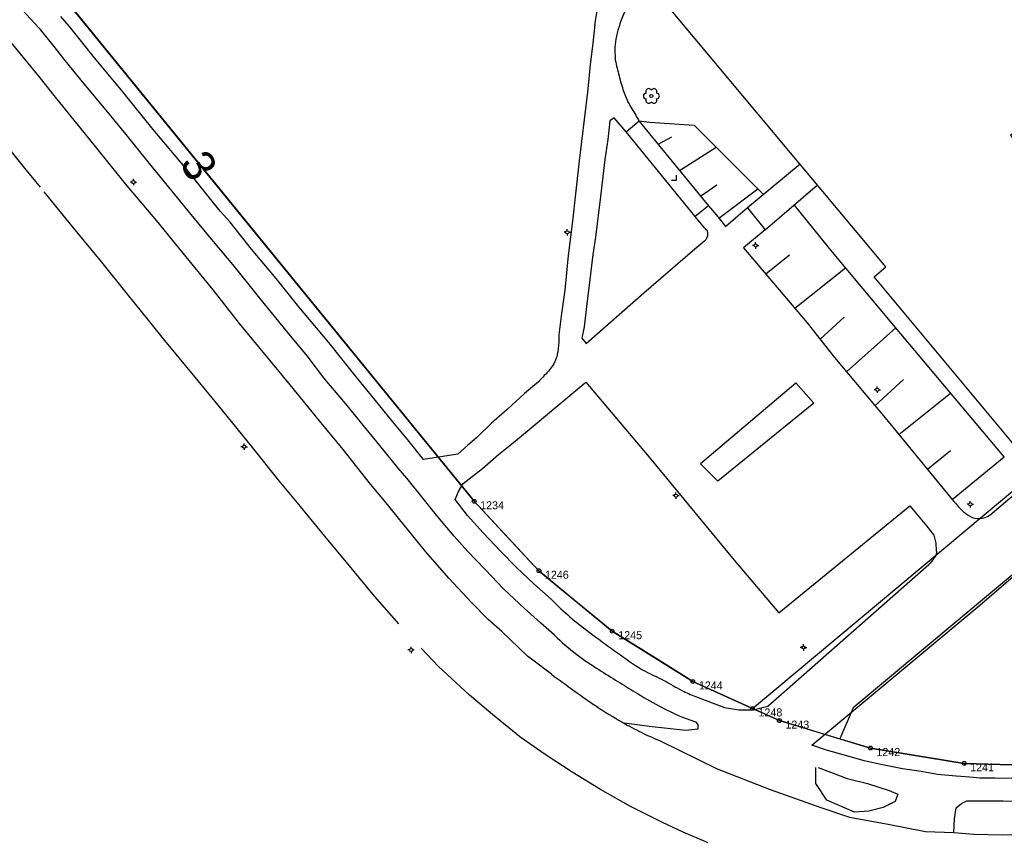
# Model space of a CAD drawing. Extents: x 1517478 to 1518189, y 6494860 to 6495389.
# Drawn here: x 1517715.6 to 1517838.6, y 6494947.3 to 6495049.6 of the extents above; entities that cross this region are included whole.
import ezdxf

# ---------------------------------------------------------------- set-up
doc = ezdxf.new("R2010")
doc.units = 0
for name, color, linetype in [('adress', 7, 'Continuous'), ('allmanbyggnad', 7, 'Continuous'), ('bro', 7, 'Continuous'), ('gc_vag', 7, 'Continuous'), ('grans', 7, 'Continuous'), ('granspunkt', 7, 'Continuous'), ('granspunkt_text', 7, 'Continuous'), ('kvartersgrans', 7, 'Continuous'), ('kvartersytor', 7, 'Continuous'), ('lovtrad', 7, 'Continuous'), ('parkeringskant', 7, 'Continuous'), ('rattighet_grans_ANV_EJ', 7, 'Continuous'), ('slant_skraffering', 7, 'Continuous'), ('slantfot', 7, 'Continuous'), ('stodmur', 7, 'Continuous'), ('stolpe_belysning', 7, 'Continuous'), ('trappa', 7, 'Continuous'), ('trappsymbol', 7, 'Continuous'), ('vagkant', 7, 'Continuous'), ('vagkant_mindre', 7, 'Continuous')]:
    doc.layers.add(name, color=color, linetype=linetype)

msp = doc.modelspace()

# ---------------------------------------------------------------- linework, layer by layer
at = {"layer": 'allmanbyggnad'}
msp.add_lwpolyline([(1517795.98, 6495052.03), (1517837.72, 6495086.69), (1517844.24, 6495078.9), (1517844.89, 6495079.4), (1517856.96, 6495064.93), (1517856.28, 6495064.33), (1517862.19, 6495057.11), (1517842.98, 6495041.23), (1517844.57, 6495039.29), (1517839.38, 6495035.07), (1517847.33, 6495025.71), (1517853.22, 6495030.6), (1517862.35, 6495019.75), (1517850.98, 6495010.13), (1517853.38, 6495007.24), (1517840.06, 6494996.19), (1517822.37, 6495017.44), (1517823.84, 6495018.69), (1517795.97, 6495052.03)], dxfattribs=at)
at = {"layer": 'bro'}
msp.add_lwpolyline([(1517813.13, 6495031.51), (1517806.55, 6495026.04), (1517808.74, 6495023.31), (1517815.3, 6495028.91)], dxfattribs=at)
at = {"layer": 'gc_vag'}
for p, q in [((1517782.84, 6495001.34), (1517786.35, 6495004.25)), ((1517783.24, 6494975.95), (1517782, 6494977.16))]:
    msp.add_line(p, q, dxfattribs=at)
for points in [[(1517718.21, 6495048.34), (1517718.04, 6495048.55), (1517715.97, 6495050.73), (1517714.5, 6495052.16), (1517712.54, 6495053.95), (1517710.97, 6495055.35), (1517708.65, 6495057.17), (1517706.66, 6495058.85), (1517705.01, 6495060.19), (1517703.14, 6495061.88)], [(1517724.81, 6495044.99), (1517723.5, 6495046.63), (1517721.86, 6495048.69), (1517720.78, 6495049.96)], [(1517721.14, 6495044.68), (1517719.93, 6495046.21), (1517718.21, 6495048.34)], [(1517787.46, 6495048.97), (1517787.21, 6495046.63), (1517786.9, 6495043.91)], [(1517737.05, 6495025.22), (1517731.83, 6495031.58), (1517728.92, 6495035.22), (1517726.43, 6495038.23), (1517723.49, 6495041.77), (1517721.14, 6495044.68)], [(1517740.66, 6495025.65), (1517736.52, 6495030.84), (1517732.32, 6495035.85), (1517728.5, 6495040.55), (1517724.81, 6495044.99)], [(1517786.9, 6495043.91), (1517786.54, 6495040.51), (1517786.18, 6495037.43), (1517785.79, 6495034.34), (1517785.53, 6495031.93)], [(1517791.38, 6495035.56), (1517789.88, 6495037.27), (1517789.36, 6495036.91), (1517789.08, 6495034.58), (1517788.74, 6495032.09)], [(1517785.53, 6495031.93), (1517785.06, 6495027.78), (1517784.67, 6495024.39), (1517784.16, 6495020.11)], [(1517788.74, 6495032.09), (1517788.2, 6495027.45), (1517787.55, 6495022.39), (1517787.24, 6495020.21)], [(1517801.66, 6495026.31), (1517802.68, 6495025.15), (1517803.84, 6495023.66)], [(1517753.76, 6495004.65), (1517751.53, 6495007.54), (1517749.08, 6495010.52), (1517745.64, 6495014.76), (1517742.46, 6495018.72), (1517739.62, 6495022.1), (1517737.05, 6495025.22)], [(1517757.49, 6495005.15), (1517754.23, 6495009.22), (1517750.51, 6495013.67), (1517747.68, 6495017.21), (1517744.59, 6495020.89), (1517741.9, 6495024.25), (1517740.66, 6495025.65)], [(1517801.2, 6495023.49), (1517800.55, 6495024.28), (1517800, 6495024.96)], [(1517784.16, 6495020.11), (1517783.72, 6495015.78), (1517783.33, 6495012.85), (1517782.99, 6495010.18), (1517782.96, 6495009.28)], [(1517787.24, 6495020.21), (1517786.85, 6495017.1), (1517786.46, 6495014.07), (1517786.15, 6495011.19), (1517785.87, 6495009.77), (1517786.38, 6495009.1)], [(1517780.43, 6495004.32), (1517778.67, 6495002.85), (1517776.54, 6495000.85), (1517774.58, 6494999.13), (1517772.72, 6494997.34), (1517771.6, 6494996.4), (1517770.34, 6494995.28), (1517766.07, 6494994.61), (1517764.1, 6494997.06), (1517762.25, 6494999.31), (1517758.99, 6495003.29), (1517757.49, 6495005.15)], [(1517760.6, 6494996.36), (1517758.17, 6494999.37), (1517756.35, 6495001.55), (1517753.76, 6495004.65)], [(1517777.33, 6494996.75), (1517780.01, 6494998.96), (1517782.84, 6495001.34)], [(1517778.68, 6494976.01), (1517776.07, 6494978.46), (1517773.82, 6494980.84), (1517771.58, 6494983.15), (1517769.9, 6494985.01), (1517767.87, 6494987.43), (1517766.05, 6494989.74), (1517763.98, 6494992.26), (1517762.92, 6494993.54), (1517760.6, 6494996.36)], [(1517782, 6494977.16), (1517779.85, 6494979.09), (1517777.68, 6494981.12), (1517775.68, 6494983.15), (1517773.54, 6494985.43), (1517771.58, 6494987.6), (1517770.04, 6494989.6), (1517770.43, 6494990.62), (1517771.02, 6494991.6), (1517773.44, 6494993.49), (1517775.43, 6494995.24), (1517777.33, 6494996.75)], [(1517782.42, 6494972.66), (1517780.67, 6494974.22), (1517778.68, 6494976.01)], [(1517800.05, 6494964.98), (1517803.66, 6494963.63), (1517805.46, 6494963.33), (1517807.27, 6494963.33), (1517809.07, 6494963.78)], [(1517798.28, 6494962.48), (1517800.05, 6494961.83), (1517800.35, 6494961.52), (1517800.35, 6494960.92), (1517798.85, 6494960.77), (1517794.64, 6494961.22), (1517791.15, 6494961.65)], [(1517821.11, 6494956.98), (1517818.95, 6494957.58), (1517816.43, 6494958.31), (1517814.6, 6494958.94)], [(1517834.33, 6494954.91), (1517832.63, 6494955.05), (1517830.29, 6494955.26), (1517828.25, 6494955.61), (1517825.91, 6494955.97), (1517823.39, 6494956.46), (1517821.11, 6494956.98)], [(1517815.39, 6494956.11), (1517819, 6494954.76), (1517821.55, 6494954.15), (1517824.26, 6494953.25), (1517825.31, 6494952.8), (1517825.01, 6494951.9), (1517823.51, 6494951.15), (1517821.7, 6494950.69), (1517819.9, 6494950.54), (1517816.44, 6494952.05), (1517815.09, 6494954.15), (1517815.09, 6494956.11)], [(1517862.88, 6494955.09), (1517860.81, 6494955.05), (1517858.46, 6494954.98), (1517854.75, 6494954.91), (1517851, 6494954.84), (1517847.43, 6494954.88), (1517844.03, 6494954.84), (1517840.85, 6494954.74), (1517837.48, 6494954.81), (1517835.56, 6494954.81), (1517834.33, 6494954.91)], [(1517832.31, 6494947.99), (1517832.41, 6494949.71), (1517832.62, 6494951.11), (1517833.29, 6494951.63), (1517833.95, 6494951.95), (1517838.47, 6494951.95), (1517843.09, 6494951.84), (1517849.01, 6494951.84), (1517853.81, 6494951.88)]]:
    msp.add_lwpolyline(points, dxfattribs=at)
for points in [[(1517786.77, 6495054.17), (1517787.37, 6495053), (1517787.7, 6495051.97), (1517787.73, 6495050.93), (1517787.44, 6495048.88)], [(1517792.29, 6495052.15), (1517791.1, 6495050.31), (1517790.48, 6495048.62), (1517790.09, 6495047.12), (1517789.98, 6495045.77), (1517790.03, 6495044.42)], [(1517790.03, 6495044.5), (1517790.5, 6495042.53), (1517791.07, 6495040.61), (1517791.75, 6495039.03), (1517792.7, 6495037.43), (1517792.99, 6495036.91)], [(1517801.22, 6495021.95), (1517801.47, 6495022.27), (1517801.59, 6495022.68), (1517801.55, 6495023.09), (1517801.19, 6495023.5)], [(1517782.96, 6495009.28), (1517782.77, 6495007.72), (1517782.46, 6495006.81), (1517782.2, 6495006.32), (1517781.68, 6495005.65), (1517780.98, 6495004.9), (1517780.43, 6495004.32)], [(1517783.24, 6494975.95), (1517785.52, 6494973.99), (1517787.71, 6494972.33), (1517790.68, 6494970.19), (1517793.75, 6494968.16), (1517796.09, 6494967.01), (1517798.33, 6494965.76), (1517800.05, 6494964.98)], [(1517782.42, 6494972.66), (1517785.21, 6494970.24), (1517787.97, 6494968.37), (1517790.36, 6494966.86), (1517792.5, 6494965.55), (1517795.47, 6494963.83), (1517798.28, 6494962.48)]]:
    msp.add_spline(points, degree=3, dxfattribs=at)
at = {"layer": 'grans'}
for p, q in [((1517807.17, 6494963.51), (1517919.72, 6495057.58)), ((1517718.21, 6495055.89), (1517772.4, 6494989.39)), ((1517772.4, 6494989.39), (1517780.49, 6494980.71)), ((1517780.49, 6494980.71), (1517789.65, 6494973.16)), ((1517789.65, 6494973.16), (1517799.72, 6494966.88)), ((1517799.72, 6494966.88), (1517807.17, 6494963.51)), ((1517807.17, 6494963.51), (1517810.53, 6494961.99)), ((1517810.53, 6494961.99), (1517821.9, 6494958.56)), ((1517821.9, 6494958.56), (1517833.61, 6494956.65)), ((1517833.61, 6494956.65), (1517845.48, 6494956.3))]:
    msp.add_line(p, q, dxfattribs=at)
at = {"layer": 'granspunkt'}
for centre in [(1517772.4, 6494989.39), (1517780.49, 6494980.71), (1517789.65, 6494973.16), (1517799.72, 6494966.88), (1517807.17, 6494963.51), (1517810.53, 6494961.99), (1517821.9, 6494958.56), (1517833.61, 6494956.65)]:
    msp.add_circle(centre, 0.237, dxfattribs=at)
at = {"layer": 'kvartersgrans'}
for points in [[(1517718.21, 6495055.89), (1517772.4, 6494989.39), (1517780.49, 6494980.71), (1517789.65, 6494973.16), (1517799.72, 6494966.88)], [(1517799.72, 6494966.88), (1517807.17, 6494963.51), (1517810.53, 6494961.99)], [(1517810.53, 6494961.99), (1517821.9, 6494958.56), (1517833.61, 6494956.65), (1517845.48, 6494956.3), (1517968.3, 6494960.82), (1517976.46, 6494961.8), (1517984.36, 6494964.1), (1517991.77, 6494967.66)]]:
    msp.add_lwpolyline(points, dxfattribs=at)
at = {"layer": 'kvartersytor'}
msp.add_lwpolyline([(1517845.48, 6494956.3), (1517833.61, 6494956.65), (1517821.9, 6494958.56), (1517816.22, 6494960.27), (1517810.53, 6494961.99), (1517807.17, 6494963.51), (1517799.72, 6494966.88), (1517794.69, 6494970.02), (1517789.65, 6494973.16), (1517785.07, 6494976.93), (1517780.49, 6494980.71), (1517776.44, 6494985.05), (1517772.4, 6494989.39), (1517745.3, 6495022.64), (1517717, 6495057.37), (1517819.97, 6495111.05)], dxfattribs=at)
at = {"layer": 'lovtrad'}
msp.add_circle((1517794.53, 6495040.02), 0.2, dxfattribs=at)
for centre, start, end in [((1517794.21, 6495040.57), 29.1347, 212.3057), ((1517794.85, 6495040.57), 329.1331, 150.8613), ((1517793.9, 6495040.01), 89.5389, 268.9887), ((1517794.21, 6495039.47), 150.5831, 330.865), ((1517794.85, 6495039.47), 209.1844, 30.8583), ((1517795.17, 6495040.02), 269.1508, 90.8733)]:
    msp.add_arc(centre, 0.366, start, end, dxfattribs=at)
at = {"layer": 'parkeringskant'}
msp.add_line((1517806.06, 6495021.07), (1517813.99, 6495011.69), dxfattribs=at)
for points in [[(1517786.38, 6495009.1), (1517793.6, 6495015.42), (1517799.97, 6495020.92), (1517801.22, 6495021.95)], [(1517813.99, 6495011.69), (1517817.41, 6495007.33), (1517823.73, 6494999.82), (1517832.13, 6494989.6)], [(1517786.35, 6495004.25), (1517794.25, 6494994.89), (1517804.87, 6494982.04)], [(1517800.68, 6494994.11), (1517812.59, 6495004.17), (1517814.82, 6495001.63), (1517802.85, 6494991.89), (1517800.68, 6494994.06)], [(1517804.87, 6494982.04), (1517810.44, 6494975.45), (1517826.82, 6494988.83)]]:
    msp.add_lwpolyline(points, dxfattribs=at)
at = {"layer": 'rattighet_grans_ANV_EJ'}
for p, q in [((1517924.99, 6495051.56), (1517819.73, 6494963.58)), ((1517819.73, 6494963.58), (1517818.07, 6494959.71))]:
    msp.add_line(p, q, dxfattribs=at)
at = {"layer": 'slant_skraffering'}
for p, q in [((1517795.39, 6495033.98), (1517797.09, 6495034.91)), ((1517798.06, 6495030.71), (1517802.63, 6495033.63)), ((1517800.68, 6495027.51), (1517802.71, 6495028.92)), ((1517802.97, 6495024.77), (1517807.84, 6495028.42)), ((1517808.82, 6495017.81), (1517811.81, 6495020.18)), ((1517812.44, 6495013.52), (1517818.8, 6495018.56)), ((1517815.62, 6495009.62), (1517818.63, 6495012.39)), ((1517818.92, 6495005.54), (1517825.06, 6495011.05)), ((1517822.47, 6495001.32), (1517826.05, 6495004.61)), ((1517825.45, 6494997.73), (1517831.92, 6495002.89)), ((1517829.03, 6494993.38), (1517831.92, 6494995.75))]:
    msp.add_line(p, q, dxfattribs=at)
at = {"layer": 'slantfot'}
for points in [[(1517792.98, 6495036.92), (1517794.29, 6495036.76), (1517799.9, 6495036.37), (1517808.6, 6495027.66)], [(1517824.82, 6495011.33), (1517817.18, 6495020.5), (1517812.41, 6495026.36)], [(1517832.13, 6494989.6), (1517838.61, 6494994.94), (1517824.82, 6495011.33)]]:
    msp.add_lwpolyline(points, dxfattribs=at)
at = {"layer": 'stodmur'}
for p, q in [((1517806.55, 6495026.04), (1517803.85, 6495023.73)), ((1517808.74, 6495023.31), (1517806.04, 6495021.07))]:
    msp.add_line(p, q, dxfattribs=at)
at = {"layer": 'stolpe_belysning'}
for p, q in [((1517729.84, 6495029.46), (1517729.84, 6495029.66)), ((1517729.64, 6495029.26), (1517729.44, 6495029.26)), ((1517729.84, 6495029.06), (1517729.84, 6495028.86)), ((1517730.04, 6495029.26), (1517730.24, 6495029.26)), ((1517784.03, 6495023.19), (1517784.03, 6495023.39)), ((1517783.83, 6495022.99), (1517783.63, 6495022.99)), ((1517784.03, 6495022.79), (1517784.03, 6495022.59)), ((1517784.23, 6495022.99), (1517784.43, 6495022.99)), ((1517807.36, 6495021.34), (1517807.16, 6495021.34)), ((1517807.56, 6495021.54), (1517807.56, 6495021.74)), ((1517807.56, 6495021.14), (1517807.56, 6495020.94)), ((1517807.76, 6495021.34), (1517807.96, 6495021.34)), ((1517822.76, 6495003.52), (1517822.76, 6495003.72)), ((1517822.56, 6495003.32), (1517822.36, 6495003.32)), ((1517822.76, 6495003.12), (1517822.76, 6495002.92)), ((1517822.96, 6495003.32), (1517823.16, 6495003.32)), ((1517743.67, 6494996.4), (1517743.67, 6494996.6)), ((1517743.47, 6494996.2), (1517743.27, 6494996.2)), ((1517743.67, 6494996), (1517743.67, 6494995.8)), ((1517743.87, 6494996.2), (1517744.07, 6494996.2)), ((1517797.4, 6494990.09), (1517797.2, 6494990.09)), ((1517797.6, 6494990.29), (1517797.6, 6494990.49)), ((1517797.8, 6494990.09), (1517798, 6494990.09)), ((1517797.6, 6494989.89), (1517797.6, 6494989.69)), ((1517834.18, 6494989.02), (1517833.98, 6494989.02)), ((1517834.38, 6494989.22), (1517834.38, 6494989.42)), ((1517834.58, 6494989.02), (1517834.78, 6494989.02)), ((1517834.38, 6494988.82), (1517834.38, 6494988.62)), ((1517764.32, 6494970.81), (1517764.12, 6494970.81)), ((1517764.52, 6494971.01), (1517764.52, 6494971.21)), ((1517764.52, 6494970.61), (1517764.52, 6494970.41)), ((1517764.72, 6494970.81), (1517764.92, 6494970.81)), ((1517813.34, 6494971.12), (1517813.14, 6494971.12)), ((1517813.54, 6494971.32), (1517813.54, 6494971.52)), ((1517813.54, 6494970.92), (1517813.54, 6494970.72)), ((1517813.74, 6494971.12), (1517813.94, 6494971.12))]:
    msp.add_line(p, q, dxfattribs=at)
for centre in [(1517729.84, 6495029.26), (1517784.03, 6495022.99), (1517807.56, 6495021.34), (1517822.76, 6495003.32), (1517743.67, 6494996.2), (1517797.6, 6494990.09), (1517834.38, 6494989.02), (1517764.52, 6494970.81), (1517813.54, 6494971.12)]:
    msp.add_circle(centre, 0.2, dxfattribs=at)
at = {"layer": 'trappa'}
msp.add_lwpolyline([(1517791.38, 6495035.56), (1517793, 6495036.93), (1517792.99, 6495036.91), (1517801.66, 6495026.31), (1517800, 6495024.96), (1517791.38, 6495035.56)], dxfattribs=at)
at = {"layer": 'trappsymbol'}
msp.add_lwpolyline([(1517797.07, 6495029.52), (1517797.67, 6495029.52), (1517797.67, 6495030.12)], dxfattribs=at)
at = {"layer": 'vagkant'}
for points in [[(1517718.21, 6495042.23), (1517716.12, 6495044.82), (1517712.42, 6495049.25)], [(1517718.21, 6495028.61), (1517716.29, 6495031.02), (1517713.45, 6495034.56), (1517709.43, 6495039.57), (1517705.29, 6495044.58), (1517702.42, 6495048.15)], [(1517728.85, 6495029.05), (1517725.08, 6495033.71), (1517719.93, 6495040.09), (1517718.21, 6495042.23)], [(1517743.08, 6495011.6), (1517739.78, 6495015.81), (1517736.06, 6495020.4), (1517732.74, 6495024.43), (1517728.85, 6495029.05)], [(1517731.71, 6495012.01), (1517729.09, 6495015.25), (1517725.91, 6495019.28), (1517722.37, 6495023.55), (1517718.67, 6495028.03)], [(1517748.05, 6494991.95), (1517744.59, 6494996.29), (1517740.99, 6495000.67), (1517737.34, 6495005.16), (1517733.77, 6495009.47), (1517731.71, 6495012.01)], [(1517759.46, 6494991.53), (1517756.05, 6494995.84), (1517753.07, 6494999.45), (1517749.43, 6495003.93), (1517747.24, 6495006.57), (1517743.08, 6495011.6)], [(1517762.98, 6494974.08), (1517759.97, 6494977.55), (1517756.82, 6494981.33), (1517753.74, 6494985.04), (1517750.34, 6494989.21), (1517748.05, 6494991.95)], [(1517774.16, 6494974.6), (1517772.06, 6494976.74), (1517769.25, 6494979.79), (1517766.35, 6494983.08), (1517763.65, 6494986.41), (1517761.2, 6494989.46), (1517759.46, 6494991.53)], [(1517782.06, 6494967.77), (1517779.06, 6494970.05), (1517775.84, 6494973.13), (1517774.16, 6494974.6)], [(1517778.12, 6494959.96), (1517774.68, 6494962.76), (1517771.81, 6494965.18), (1517767.91, 6494968.78), (1517765.76, 6494971.04)], [(1517801.64, 6494946.72), (1517798.5, 6494948.05), (1517795.91, 6494949.27), (1517791.92, 6494951.27), (1517788.17, 6494953.37), (1517784.63, 6494955.54), (1517781.16, 6494957.82), (1517778.12, 6494959.96)], [(1517795.62, 6494959.46), (1517802.76, 6494955.96), (1517809.37, 6494953.4), (1517815.69, 6494951.15), (1517819.3, 6494949.94), (1517824.11, 6494949.04), (1517828.77, 6494948.14), (1517832.31, 6494947.99)], [(1517832.31, 6494947.99), (1517834.83, 6494947.82), (1517838.37, 6494947.71), (1517842.24, 6494947.74), (1517847.89, 6494947.75), (1517851.78, 6494947.96), (1517854.13, 6494948.06)]]:
    msp.add_lwpolyline(points, dxfattribs=at)
msp.add_spline([(1517782.06, 6494967.77), (1517784.9, 6494965.71), (1517788.07, 6494963.52), (1517791.25, 6494961.59), (1517793.54, 6494960.39), (1517795.62, 6494959.46)], degree=3, dxfattribs=at)
at = {"layer": 'vagkant_mindre'}
msp.add_line((1517809.07, 6494963.78), (1517829.2, 6494981.47), dxfattribs=at)
for points in [[(1517814.6, 6494958.94), (1517835.57, 6494976.43), (1517848.02, 6494987.1), (1517878.6, 6495013.87), (1517874.09, 6495020.04)], [(1517836.85, 6494987.68), (1517842.85, 6494992.77), (1517840.06, 6494996.19)], [(1517826.82, 6494988.83), (1517828.89, 6494986.34), (1517829.82, 6494985.15), (1517830.08, 6494984.16), (1517830.13, 6494983.23)]]:
    msp.add_lwpolyline(points, dxfattribs=at)
for points in [[(1517832.13, 6494989.6), (1517833.76, 6494987.89), (1517834.9, 6494987.27), (1517836.25, 6494987.38), (1517836.97, 6494987.74)], [(1517830.13, 6494983.23), (1517830.13, 6494982.81), (1517829.84, 6494982.28), (1517829.2, 6494981.47)]]:
    msp.add_spline(points, degree=3, dxfattribs=at)

# ---------------------------------------------------------------- texts
at = {"layer": 'adress'}
msp.add_text('3', height=4, rotation=299.2317, dxfattribs=at).set_placement((1517735.56, 6495031.67))
at = {"layer": 'granspunkt_text'}
for s, p in [('1234', (1517773.15, 6494988.39)), ('1246', (1517781.24, 6494979.71)), ('1245', (1517790.4, 6494972.16)), ('1244', (1517800.47, 6494965.88)), ('1248', (1517807.92, 6494962.51)), ('1243', (1517811.28, 6494960.99)), ('1242', (1517822.65, 6494957.56)), ('1241', (1517834.36, 6494955.65))]:
    msp.add_text(s, height=1, dxfattribs=at).set_placement(p)

doc.saveas('drawing.dxf')
